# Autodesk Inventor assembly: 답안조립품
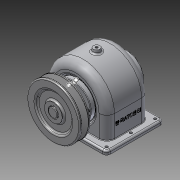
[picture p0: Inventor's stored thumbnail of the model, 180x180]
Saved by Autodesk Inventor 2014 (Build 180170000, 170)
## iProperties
Created: 2015-09
Part Number: 답안조립품
Document SubType Name: Assembly
Designer: Administrator
Author: Administrator
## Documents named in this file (14)
- C:\Users\Administrator\Desktop\450907V1049\답안조립품.iam
- C:\Users\Administrator\Desktop\450907V1049\1-본체.ipt
- C:\Users\Administrator\Desktop\450907V1049\V-벨트풀리.ipt
- C:\Users\Administrator\Desktop\450907V1049\뒤커버.ipt
- C:\Users\Administrator\Desktop\450907V1049\멈춤나사 - M4x10.ipt
- C:\Users\Administrator\Desktop\450907V1049\베어링 6203.ipt
- C:\Users\Administrator\Desktop\450907V1049\볼트 M3 x 8.ipt
- C:\Users\Administrator\Desktop\450907V1049\볼트 M3 x 10.ipt
- C:\Users\Administrator\Desktop\450907V1049\스퍼기어.ipt
- C:\Users\Administrator\Desktop\450907V1049\앞커버.ipt
- C:\Users\Administrator\Desktop\450907V1049\오일 실 17 32 8.ipt
- C:\Users\Administrator\Desktop\450907V1049\축.ipt
- C:\Users\Administrator\Desktop\450907V1049\키 - 5 x 5 x 18.ipt
- C:\Users\Administrator\Desktop\450907V1049\키 - 6 x 6 x 22.ipt
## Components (10 placed, 4 different names)
1. 1-본체:1
2. V-벨트풀리:1
3. ISO 4762 M3 x 10:1
4. ISO 4762 M3 x 10:2
5. ISO 4762 M3 x 10:3
6. ISO 4762 M3 x 10:4
7. ISO 4762 M3 x 8:1
8. ISO 4762 M3 x 8:2
9. ISO 4762 M3 x 8:3
10. ISO 4762 M3 x 8:4
